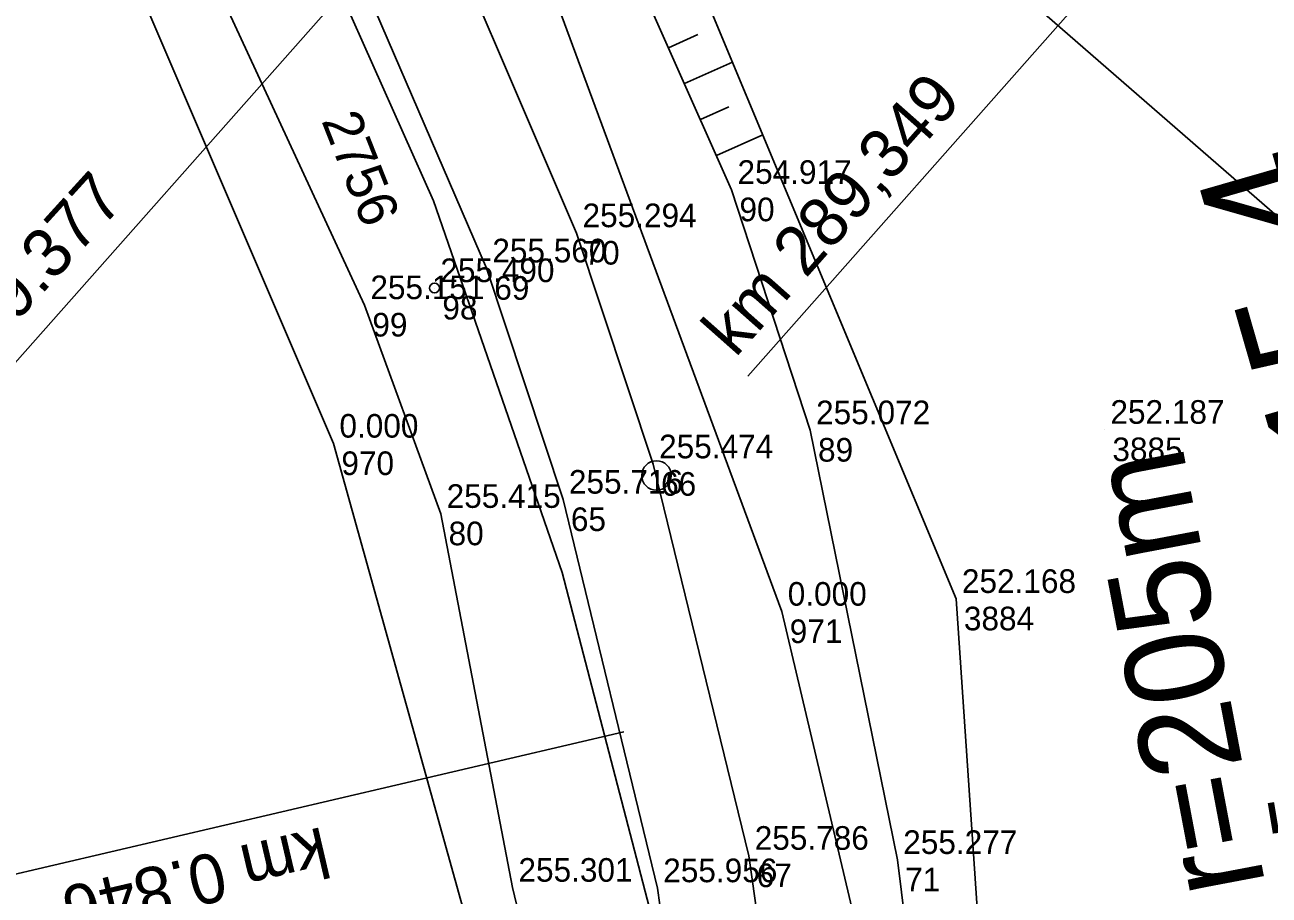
# Model space of a CAD drawing. Extents: x -496688 to -495455, y -1089309 to -1088026.
# Drawn here: x -495849.3 to -495786, y -1088831.6 to -1088787.4 of the extents above; entities that cross this region are included whole.
import ezdxf

# ---------------------------------------------------------------- set-up
doc = ezdxf.new("R2010")
doc.units = 0
for name, color, linetype in [('Vrstva 1', 7, 'Continuous'), ('Vrstva 3', 7, 'Continuous'), ('Vrstva 48', 7, 'Continuous'), ('Vrstva 49', 7, 'Continuous'), ('Vrstva 53', 7, 'Continuous'), ('Vrstva 55', 7, 'Continuous'), ('Vrstva 57', 7, 'Continuous'), ('Vrstva 60', 7, 'Continuous'), ('Vrstva 61', 7, 'Continuous'), ('Vrstva 7', 7, 'Continuous')]:
    doc.layers.add(name, color=color, linetype=linetype)

msp = doc.modelspace()

# ---------------------------------------------------------------- linework, layer by layer
at = {"layer": 'Vrstva 1'}
for p, q in [((-495811.199, -1088761.005), (-495868.035, -1088825.148)), ((-495818.828, -1088823.313), (-495897.15, -1088841.634))]:
    msp.add_line(p, q, dxfattribs=at)
for points in [[(-495809.634, -1088849.637), (-495812.479, -1088829.606), (-495817.339, -1088809.711), (-495821.231, -1088797.964), (-495829.889, -1088777.756), (-495839.468, -1088760.605), (-495852.198, -1088742.475), (-495858.955, -1088734.298), (-495866.249, -1088726.179), (-495875.462, -1088716.542)], [(-495856.572, -1088744.636), (-495843.38, -1088763.743), (-495834.304, -1088780.085), (-495825.818, -1088799.752), (-495821.924, -1088811.506), (-495817.129, -1088831.255), (-495814.517, -1088849.896)]]:
    msp.add_lwpolyline(points, dxfattribs=at)
msp.add_circle((-495828.458, -1088800.755), 0.25, dxfattribs=at)
at = {"layer": 'Vrstva 3'}
msp.add_line((-495812.535, -1088805.234), (-495790.007, -1088779.778), dxfattribs=at)
at = {"layer": 'Vrstva 48'}
for p, q in [((-495815.073, -1088787.877), (-495816.566, -1088788.541)), ((-495813.309, -1088789.281), (-495815.753, -1088790.368)), ((-495813.5, -1088791.554), (-495814.94, -1088792.195)), ((-495811.771, -1088792.973), (-495814.127, -1088794.022))]:
    msp.add_line(p, q, dxfattribs=at)
at = {"layer": 'Vrstva 49'}
msp.add_line((-495820.615, -1088771.746), (-495801.946, -1088816.553), dxfattribs=at)
for points in [[(-495874.831, -1088740.506), (-495871.378, -1088742.474), (-495861.997, -1088751.266), (-495849.751, -1088765.614), (-495840.618, -1088783.025), (-495832.017, -1088801.621), (-495828.141, -1088812.229), (-495824.489, -1088831.23), (-495819.19, -1088853.259), (-495818.637, -1088882.621), (-495817.153, -1088910.251), (-495817.638, -1088917.871)], [(-495820.542, -1088767.266), (-495823.352, -1088769.277), (-495822.701, -1088774.752), (-495813.353, -1088795.762), (-495809.36, -1088807.978), (-495804.929, -1088829.819), (-495802.497, -1088849.398)], [(-495801.946, -1088816.553), (-495799.221, -1088856.449), (-495797.287, -1088884.444), (-495797.7, -1088915.73)]]:
    msp.add_lwpolyline(points, dxfattribs=at)
at = {"layer": 'Vrstva 53'}
for points in [[(-496028.63, -1089095.5), (-495988.92, -1089093.88), (-495950.11, -1089084.84), (-495944.93, -1089082.27), (-495928.74, -1089074.25), (-495900.77, -1089053.63), (-495889.38, -1089043.24), (-495874.93, -1089030.05), (-495865.93, -1089019.09), (-495857.07, -1089007.86), (-495847.95, -1088993.74), (-495833.43, -1088965.11), (-495819.03, -1088928.06), (-495817.99, -1088913.23), (-495820.47, -1088875.16), (-495825.59, -1088837.35), (-495833.59, -1088808.66), (-495849.13, -1088772.39), (-495858.89, -1088755.75), (-495866.6, -1088751.5)], [(-495820.95, -1088766.37), (-495836.28, -1088760.05), (-495822.59, -1088785.27), (-495810.8, -1088817.2), (-495805.63, -1088839.06), (-495801.74, -1088870.1), (-495801.67, -1088898.42), (-495801.94, -1088953.23), (-495800.51, -1088960.04), (-495800.3, -1088973.88), (-495761.53, -1088987.72), (-495761.24, -1088987.38), (-495760.41, -1088988.12), (-495744.16, -1088993.92), (-495645.99, -1088956.12), (-495627.19, -1088948.89), (-495666.59, -1088906.58), (-495728.02, -1088847.18), (-495820.854, -1088766.454)]]:
    msp.add_lwpolyline(points, dxfattribs=at)
at = {"layer": 'Vrstva 55'}
for p, q in [((-495836.7, -1088777.99), (-495828.5, -1088796.33)), ((-495828.5, -1088796.33), (-495821.97, -1088815.21)), ((-495821.97, -1088815.21), (-495816.93, -1088834.58))]:
    msp.add_line(p, q, dxfattribs=at)
at = {"layer": 'Vrstva 60'}
for p, q in [((-495813.353, -1088795.762), (-495813.353, -1088795.762)), ((-495813.353, -1088795.762), (-495813.353, -1088795.762)), ((-495821.231, -1088797.964), (-495821.231, -1088797.964)), ((-495821.231, -1088797.964), (-495821.231, -1088797.964)), ((-495825.818, -1088799.752), (-495825.818, -1088799.752)), ((-495825.818, -1088799.752), (-495825.818, -1088799.752)), ((-495828.458, -1088800.755), (-495828.458, -1088800.755)), ((-495828.458, -1088800.755), (-495828.458, -1088800.755)), ((-495832.017, -1088801.621), (-495832.017, -1088801.621)), ((-495832.017, -1088801.621), (-495832.017, -1088801.621)), ((-495809.36, -1088807.978), (-495809.36, -1088807.978)), ((-495809.36, -1088807.978), (-495809.36, -1088807.978)), ((-495794.397, -1088807.955), (-495794.397, -1088807.955)), ((-495794.397, -1088807.955), (-495794.397, -1088807.955)), ((-495833.59, -1088808.66), (-495833.59, -1088808.66)), ((-495833.59, -1088808.66), (-495833.59, -1088808.66)), ((-495817.339, -1088809.711), (-495817.339, -1088809.711)), ((-495817.339, -1088809.711), (-495817.339, -1088809.711)), ((-495821.924, -1088811.506), (-495821.924, -1088811.506)), ((-495821.924, -1088811.506), (-495821.924, -1088811.506)), ((-495828.141, -1088812.229), (-495828.141, -1088812.229)), ((-495828.141, -1088812.229), (-495828.141, -1088812.229)), ((-495801.946, -1088816.553), (-495801.946, -1088816.553)), ((-495801.946, -1088816.553), (-495801.946, -1088816.553)), ((-495810.8, -1088817.2), (-495810.8, -1088817.2)), ((-495810.8, -1088817.2), (-495810.8, -1088817.2)), ((-495812.479, -1088829.606), (-495812.479, -1088829.606)), ((-495812.479, -1088829.606), (-495812.479, -1088829.606)), ((-495804.929, -1088829.819), (-495804.929, -1088829.819)), ((-495804.929, -1088829.819), (-495804.929, -1088829.819)), ((-495824.489, -1088831.23), (-495824.489, -1088831.23)), ((-495824.489, -1088831.23), (-495824.489, -1088831.23)), ((-495817.129, -1088831.255), (-495817.129, -1088831.255)), ((-495817.129, -1088831.255), (-495817.129, -1088831.255))]:
    msp.add_line(p, q, dxfattribs=at)
at = {"layer": 'Vrstva 7'}
msp.add_circle((-495817.173, -1088810.283), 0.75, dxfattribs=at)

# ---------------------------------------------------------------- texts
at = {"layer": 'Vrstva 1'}
for s, height, rotation, p in [('km 289.377', 2.5, 47.75531, (-495855.845, -1088809.274)), ('r=205m', 5, 100.73695, (-495786.209, -1088831.1)), ('5', 3, 99.46099, (-495782.827, -1088828.319)), ('km 0.846', 2.5, 193.16584, (-495834.156, -1088828.13))]:
    msp.add_text(s, height=height, rotation=rotation, dxfattribs=at).set_placement(p)
at = {"layer": 'Vrstva 3'}
msp.add_text('km 289,349', height=2.5, rotation=48.49196, dxfattribs=at).set_placement((-495813.161, -1088804.335))
at = {"layer": 'Vrstva 57'}
msp.add_text('2756', height=2, rotation=291.52314, dxfattribs=at).set_placement((-495834.22, -1088792.247))
at = {"layer": 'Vrstva 60'}
for s, p in [('90', (-495812.953, -1088797.362)), ('90', (-495812.953, -1088797.362)), ('70', (-495820.831, -1088799.564)), ('70', (-495820.831, -1088799.564)), ('69', (-495825.418, -1088801.352)), ('69', (-495825.418, -1088801.352)), ('98', (-495828.058, -1088802.355)), ('98', (-495828.058, -1088802.355)), ('99', (-495831.617, -1088803.221)), ('99', (-495831.617, -1088803.221)), ('89', (-495808.96, -1088809.578)), ('89', (-495808.96, -1088809.578)), ('3885', (-495793.997, -1088809.555)), ('3885', (-495793.997, -1088809.555)), ('970', (-495833.19, -1088810.26)), ('970', (-495833.19, -1088810.26)), ('66', (-495816.939, -1088811.311)), ('66', (-495816.939, -1088811.311)), ('65', (-495821.524, -1088813.106)), ('65', (-495821.524, -1088813.106)), ('80', (-495827.741, -1088813.829)), ('80', (-495827.741, -1088813.829)), ('3884', (-495801.546, -1088818.153)), ('3884', (-495801.546, -1088818.153)), ('971', (-495810.4, -1088818.8)), ('971', (-495810.4, -1088818.8)), ('67', (-495812.079, -1088831.206)), ('67', (-495812.079, -1088831.206)), ('71', (-495804.529, -1088831.419)), ('71', (-495804.529, -1088831.419))]:
    msp.add_text(s, height=1.2, dxfattribs=at).set_placement(p)
at = {"layer": 'Vrstva 61'}
for s, p in [('254.917', (-495813.053, -1088795.462)), ('254.917', (-495813.053, -1088795.462)), ('255.294', (-495820.931, -1088797.664)), ('255.294', (-495820.931, -1088797.664)), ('255.560', (-495825.518, -1088799.452)), ('255.560', (-495825.518, -1088799.452)), ('255.490', (-495828.158, -1088800.455)), ('255.490', (-495828.158, -1088800.455)), ('255.151', (-495831.717, -1088801.321)), ('255.151', (-495831.717, -1088801.321)), ('255.072', (-495809.06, -1088807.678)), ('255.072', (-495809.06, -1088807.678)), ('252.187', (-495794.097, -1088807.655)), ('252.187', (-495794.097, -1088807.655)), ('0.000', (-495833.29, -1088808.36)), ('0.000', (-495833.29, -1088808.36)), ('255.474', (-495817.039, -1088809.411)), ('255.474', (-495817.039, -1088809.411)), ('255.716', (-495821.624, -1088811.206)), ('255.716', (-495821.624, -1088811.206)), ('255.415', (-495827.841, -1088811.929)), ('255.415', (-495827.841, -1088811.929)), ('252.168', (-495801.646, -1088816.253)), ('252.168', (-495801.646, -1088816.253)), ('0.000', (-495810.5, -1088816.9)), ('0.000', (-495810.5, -1088816.9)), ('255.786', (-495812.179, -1088829.306)), ('255.786', (-495812.179, -1088829.306)), ('255.277', (-495804.629, -1088829.519)), ('255.277', (-495804.629, -1088829.519)), ('255.301', (-495824.189, -1088830.93)), ('255.301', (-495824.189, -1088830.93)), ('255.956', (-495816.829, -1088830.955)), ('255.956', (-495816.829, -1088830.955))]:
    msp.add_text(s, height=1.2, dxfattribs=at).set_placement(p)
at = {"layer": 'Vrstva 7'}
msp.add_text('115.4', height=6, rotation=106.0648, dxfattribs=at).set_placement((-495778.492, -1088812.459))

doc.saveas('drawing.dxf')
